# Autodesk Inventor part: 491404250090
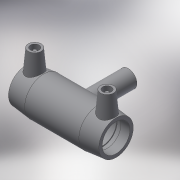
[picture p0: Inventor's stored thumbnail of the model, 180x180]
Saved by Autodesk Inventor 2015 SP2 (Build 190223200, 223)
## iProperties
Created: 2017-06
Part Number: 491404250090
Material: Generic
Description: PLASSON REDUCING TEE 250x90x250
Document SubType Name: Modeling
Designer: KIM
Mass: 57.3761 g
Surface Area: 241.06 cm^2
Volume: 57.3761 cm^3
Density: 1 g/cm^3
Appearance: Default
Author: KIM
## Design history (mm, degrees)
derived "491404.ipt"
feature "Solid1::491404.ipt"
tag "TaggingFeature1"
body "Solid1"
other parameters: "d0" = 538, "d2" = 326, "d3" = 129, "d4" = 107.6, "d5" = 293.4, "d6" = 237.5, "d8" = 168 deg, "d10" = 51.6, "d11" = 17.2, "d13" = 538, "d14" = 17.6296, "d17" = 225, "d19" = 3.52592, "d20" = 168 deg, "d22" = 303.18, "d23" = 326, "d25" = 135 deg, "d26" = 376.6, "d29" = 152, "d30" = 15, "d31" = 215.2, "d34" = 5 deg, "d35" = 15, "d39" = 5 deg, "d41" = 4, "d42" = 14, "d43" = 0, "d45" = 4, "d46" = 6, "d47" = 0, "d48" = -235, "d51" = 0, "d52" = 72, "d54" = 0, "d55" = 293.4, "d56" = 326, "d57" = 188.3, "d58" = 135 deg, "d59" = 129, "d60" = 129, "d61" = 135 deg, "d62" = 235, "d72" = 244.79, "d73" = 122.395, "d74" = -235, "d75" = 94.5, "d77" = 0, "d78" = 72, "d80" = 0, "d82" = 72, "d83" = 0, "d84" = 3, "d85" = 0, "d86" = 43, "d87" = 297.1164, "d88" = 17.2, "d89" = 3, "d90" = 0, "L_" = 538, "L_1" = 129, "D_" = 326, "A_" = 152, "d_2" = 12, "H_" = 235
